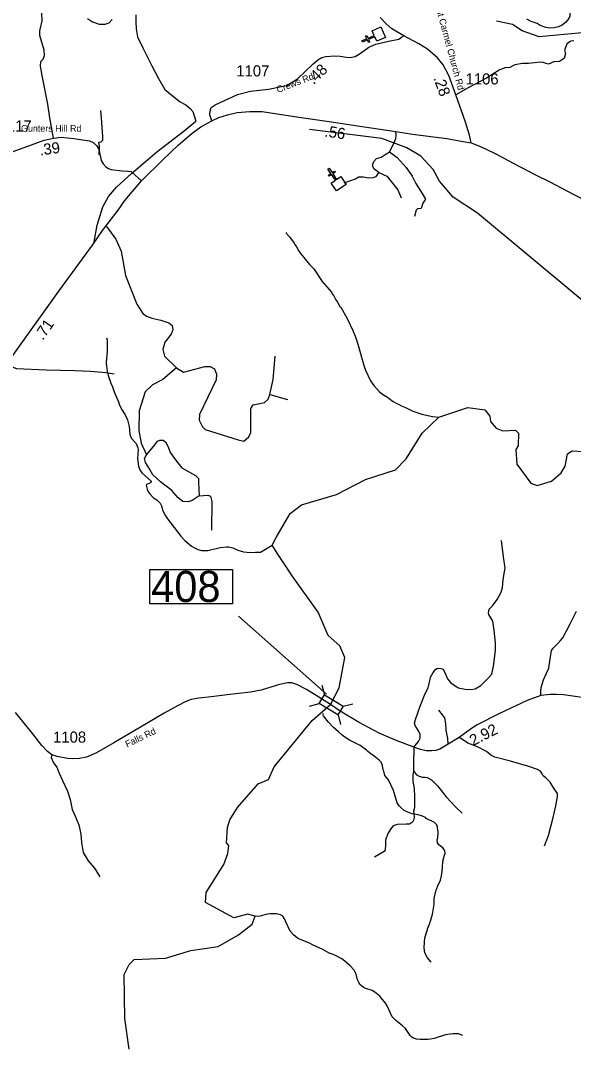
# Model space of a CAD drawing. Extents: x 1248089 to 1457196, y 820910 to 988753.
# Drawn here: x 1338152 to 1344378, y 848615 to 860169 of the extents above; entities that cross this region are included whole.
import ezdxf

# ---------------------------------------------------------------- set-up
doc = ezdxf.new("R2010")
doc.units = 0
for name, color, linetype in [('Exist Cultural Church CELL', 7, 'Continuous'), ('Exist Geographical Mountain Summit Label', 7, 'Continuous'), ('Exist Hydrographic Creek Single Shore', 7, 'Continuous'), ('Exist Hydrographic Misc Water Feature', 7, 'Continuous'), ('Exist Road Non-System Type 51', 7, 'Continuous'), ('Exist Road Primary NC Attributed', 7, 'Continuous'), ('Exist Road Secondary Structure Standard Bridge CELL', 7, 'Continuous'), ('Exist Road Secondary Structure Standard Bridge Number Label', 7, 'Continuous'), ('Exist Road Secondary Type 51 Attributed', 7, 'Continuous'), ('Exist Road Secondary Type 51 Label', 7, 'Continuous'), ('Prop CMT Slope Fill', 7, 'Continuous'), ('Prop GRAU CAT1 Cell', 7, 'Continuous'), ('Prop Lane Lines', 7, 'Continuous')]:
    doc.layers.add(name, color=color, linetype=linetype)

msp = doc.modelspace()

# ---------------------------------------------------------------- linework, layer by layer
at = {"layer": 'Exist Cultural Church CELL'}
for points in [[(1342164, 859935), (1342141, 859987), (1342071, 859957), (1342084, 859927), (1342069, 859921), (1342057, 859950), (1342001, 859926), (1341995, 859941), (1342050, 859965), (1342037, 859994), (1342052, 860001), (1342065, 859971), (1342135, 860002), (1342112, 860055), (1342209, 860097), (1342262, 859977)], [(1341650, 858339), (1341697, 858370), (1341655, 858434), (1341629, 858416), (1341620, 858429), (1341646, 858447), (1341613, 858497), (1341626, 858506), (1341660, 858456), (1341686, 858474), (1341695, 858460), (1341669, 858443), (1341711, 858379), (1341759, 858411), (1341818, 858323), (1341709, 858250)]]:
    msp.add_lwpolyline(points, close=True, dxfattribs=at)
at = {"layer": 'Exist Hydrographic Creek Single Shore'}
for points in [[(1341642, 852465), (1341739, 852654), (1341803, 852995), (1341747, 853127), (1341615, 853242), (1341503, 853505), (1341212, 853916), (1341125, 854046), (1341049, 854158), (1340984, 854262), (1341031, 854346), (1341187, 854619), (1341314, 854715), (1341708, 854832), (1342037, 854999), (1342373, 855110), (1342493, 855233), (1342674, 855521), (1342861, 855704), (1343189, 855810), (1343380, 855786), (1343437, 855713), (1343444, 855654), (1343509, 855577), (1343584, 855549), (1343726, 855556), (1343758, 855522), (1343755, 855378), (1343729, 855339), (1343742, 855172), (1343896, 854958), (1343970, 854934), (1344130, 854980), (1344240, 855076), (1344284, 855151), (1344312, 855291), (1344362, 855323), (1344487, 855314)], [(1340510, 851166), (1340597, 851305), (1340828, 851573), (1340946, 851623), (1341007, 851763), (1341436, 852287), (1341642, 852465)], [(1339377, 848583), (1339327, 848931), (1339321, 849424), (1339374, 849537), (1339433, 849595), (1339784, 849611), (1340069, 849697), (1340379, 849740), (1340607, 849871), (1340759, 849994), (1340793, 850081), (1340706, 850107), (1340555, 850063), (1340236, 850235), (1340243, 850351), (1340443, 850664), (1340485, 850789), (1340496, 850880), (1340471, 850907), (1340483, 851081), (1340510, 851166)]]:
    msp.add_lwpolyline(points, dxfattribs=at)
at = {"layer": 'Exist Hydrographic Misc Water Feature'}
for points in [[(1344475, 860032), (1343990, 859986), (1343800, 860055), (1343693, 860126), (1343510, 860163)], [(1345844, 854850), (1345727, 855194), (1345671, 855313), (1345336, 855629), (1345143, 855908), (1345055, 856110), (1344998, 856561), (1344926, 856681), (1344459, 857032), (1343296, 858000), (1343024, 858180), (1342870, 858360), (1342798, 858493), (1342659, 858640), (1342503, 858735), (1342222, 858839), (1341407, 858941)], [(1341142, 857781), (1341143, 857773), (1341180, 857732), (1341233, 857663), (1341240, 857646), (1341260, 857622), (1341287, 857573), (1341310, 857541), (1341407, 857423), (1341454, 857373), (1341547, 857231), (1341629, 857141), (1341652, 857109), (1341660, 857093), (1341679, 857068), (1341704, 857022), (1341722, 856999), (1341749, 856950), (1341757, 856942), (1341830, 856813), (1341893, 856679), (1341927, 856594), (1341949, 856526), (1342020, 856274), (1342037, 856232), (1342094, 856110), (1342129, 856058), (1342195, 855988), (1342238, 855955), (1342284, 855928), (1342349, 855880), (1342388, 855855), (1342422, 855841), (1342432, 855832), (1342485, 855811), (1342570, 855771), (1342670, 855735), (1342789, 855708), (1342861, 855704)], [(1339120, 856597), (1339126, 856573), (1339129, 856533), (1339127, 856445), (1339124, 856397), (1339119, 856375), (1339118, 856309), (1339128, 856221), (1339139, 856173), (1339169, 856084), (1339188, 856044), (1339206, 855987), (1339256, 855874), (1339263, 855850), (1339290, 855793), (1339329, 855728), (1339355, 855672), (1339376, 855599), (1339384, 855511), (1339391, 855487), (1339403, 855463), (1339453, 855405), (1339474, 855357), (1339476, 855341), (1339471, 855237), (1339479, 855149), (1339497, 855108), (1339518, 855076), (1339623, 854981), (1339622, 854972), (1339617, 854965), (1339609, 854958), (1339595, 854952), (1339579, 854948), (1339571, 854943), (1339567, 854935), (1339578, 854890), (1339593, 854858), (1339605, 854842), (1339651, 854795), (1339687, 854772), (1339724, 854733), (1339739, 854703), (1339756, 854646), (1339783, 854590), (1339806, 854557), (1339958, 854361), (1340003, 854312), (1340079, 854251), (1340119, 854226), (1340150, 854211), (1340190, 854200), (1340230, 854199), (1340262, 854202), (1340399, 854233), (1340471, 854243), (1340479, 854241), (1340495, 854243), (1340543, 854230), (1340598, 854204), (1340662, 854185), (1340742, 854177), (1340796, 854182), (1340854, 854182), (1340984, 854262)], [(1342776, 849563), (1342735, 849612), (1342704, 849669), (1342697, 849725), (1342699, 849791), (1342704, 849837), (1342734, 849932), (1342734, 849940), (1342760, 850003), (1342760, 850011), (1342768, 850027), (1342790, 850107), (1342809, 850218), (1342810, 850282), (1342819, 850330), (1342832, 850378), (1342841, 850393), (1342849, 850425), (1342879, 850488), (1342892, 850536), (1342901, 850584), (1342902, 850642), (1342907, 850696), (1342912, 850704), (1342912, 850720), (1342932, 850791), (1342930, 850815), (1342921, 850833), (1342907, 850852), (1342862, 850885), (1342848, 850909), (1342845, 850941), (1342849, 850965), (1342853, 851029), (1342843, 851105), (1342837, 851115), (1342813, 851138), (1342718, 851184), (1342711, 851192), (1342679, 851209), (1342631, 851224), (1342560, 851236), (1342520, 851249), (1342472, 851274), (1342437, 851303), (1342414, 851327), (1342394, 851360), (1342353, 851497), (1342296, 851618), (1342253, 851667), (1342242, 851715), (1342235, 851732), (1342226, 851780), (1342213, 851816), (1342189, 851841), (1342134, 851886), (1342095, 851911), (1342063, 851936), (1342048, 851952), (1341977, 852006), (1341858, 852063), (1341803, 852098), (1341756, 852135), (1341732, 852159), (1341673, 852211), (1341619, 852266), (1341562, 852340), (1341558, 852348), (1341559, 852366)], [(1343131, 848739), (1343115, 848747), (1343083, 848756), (1343020, 848759), (1342937, 848747), (1342810, 848706), (1342770, 848697), (1342738, 848694), (1342650, 848694), (1342610, 848697), (1342576, 848708), (1342557, 848720), (1342541, 848737), (1342485, 848816), (1342453, 848849), (1342379, 848909), (1342338, 848950), (1342317, 848990), (1342282, 849071), (1342263, 849103), (1342197, 849181), (1342142, 849226), (1342110, 849245), (1342039, 849269), (1342015, 849281), (1341988, 849302), (1341972, 849318), (1341960, 849334), (1341945, 849367), (1341930, 849431), (1341909, 849474), (1341865, 849525), (1341802, 849574), (1341770, 849603), (1341691, 849645), (1341644, 849662), (1341636, 849662), (1341549, 849712), (1341454, 849754), (1341398, 849784), (1341295, 849822), (1341272, 849835), (1341226, 849872), (1341189, 849913), (1341140, 850018), (1341126, 850052), (1341105, 850081), (1341081, 850099), (1341034, 850110), (1340960, 850110), (1340913, 850103), (1340865, 850086), (1340833, 850079), (1340793, 850081)]]:
    msp.add_lwpolyline(points, dxfattribs=at)
at = {"layer": 'Exist Road Non-System Type 51'}
msp.add_line((1340958, 855957), (1341157, 855902), dxfattribs=at)
for points in [[(1344045, 861034), (1344103, 860945), (1344175, 860858), (1344223, 860819), (1344273, 860798), (1344310, 860792), (1344349, 860775), (1344357, 860769), (1344368, 860748), (1344364, 860676), (1344353, 860564), (1344336, 860313), (1344338, 860220), (1344324, 860191), (1344291, 860150), (1344252, 860118), (1344210, 860100), (1344161, 860087), (1344113, 860085), (1344066, 860092), (1344001, 860112), (1343968, 860137), (1343900, 860160), (1343851, 860183)], [(1338483, 859075), (1338458, 859229), (1338397, 859550), (1338378, 859654), (1338381, 859707), (1338409, 859734), (1338424, 859777), (1338418, 859836), (1338369, 860002), (1338370, 860053), (1338397, 860167), (1338391, 860256), (1338345, 860382), (1338342, 860456)], [(1339450, 860235), (1339450, 860155), (1339453, 860075), (1339471, 859985), (1339530, 859862), (1339631, 859659), (1339704, 859516), (1339778, 859392), (1339861, 859325), (1339950, 859254), (1340015, 859220), (1340064, 859177), (1340092, 859143), (1340127, 859034)], [(1338905, 860192), (1338963, 860155), (1339037, 860130), (1339105, 860130), (1339151, 860145), (1339185, 860179)], [(1344380, 859941), (1344347, 859937), (1344332, 859931), (1344303, 859904), (1344295, 859883), (1344278, 859837), (1344289, 859798), (1344272, 859740), (1344243, 859722), (1344220, 859707), (1344158, 859703), (1344098, 859676), (1344072, 859685), (1344037, 859697), (1344004, 859699), (1343940, 859691), (1343871, 859687), (1343805, 859687), (1343716, 859670), (1343660, 859639), (1343605, 859637), (1343541, 859610), (1343398, 859521), (1343192, 859410), (1343055, 859332)], [(1338522, 858844), (1338483, 859075)], [(1339037, 858656), (1339040, 858749), (1339034, 858799), (1339061, 858802), (1339080, 858823), (1339080, 858860), (1339064, 859073), (1339058, 859156)], [(1339402, 858447), (1339531, 858554), (1339687, 858691), (1339994, 858928), (1340127, 859034)], [(1342306, 858692), (1342356, 858783), (1342379, 858839), (1342382, 858879), (1342379, 858918)], [(1342185, 858458), (1342129, 858499), (1342115, 858539), (1342132, 858582), (1342162, 858615), (1342212, 858632), (1342259, 858659), (1342306, 858692)], [(1342306, 858692), (1342392, 858626), (1342496, 858515), (1342563, 858418), (1342603, 858335), (1342676, 858221), (1342710, 858158), (1342683, 858111), (1342663, 858051), (1342623, 858047), (1342606, 858034), (1342589, 857964)], [(1338980, 857676), (1339014, 857863), (1339080, 858070), (1339144, 858186), (1339234, 858293), (1339402, 858447)], [(1341795, 858342), (1341922, 858385), (1341958, 858408), (1342012, 858408), (1342068, 858398), (1342122, 858402), (1342155, 858412), (1342169, 858428), (1342185, 858458)], [(1342185, 858458), (1342276, 858418), (1342312, 858375), (1342399, 858261), (1342436, 858174)], [(1339120, 857849), (1339224, 857706), (1339284, 857572), (1339334, 857298), (1339461, 856976), (1339529, 856871), (1339569, 856839), (1339630, 856817), (1339733, 856795), (1339821, 856765), (1339860, 856733), (1339868, 856687), (1339848, 856638), (1339777, 856547), (1339755, 856464), (1339773, 856391), (1339910, 856258)], [(1337996, 856304), (1338077, 856260), (1338106, 856250), (1338441, 856237), (1338764, 856227), (1338935, 856222), (1339115, 856206), (1339207, 856189)], [(1340958, 855957), (1340997, 856125), (1341020, 856391)], [(1339910, 856258), (1339754, 856125), (1339637, 856066), (1339555, 855988), (1339488, 855775), (1339485, 855554), (1339510, 855409), (1339569, 855277)], [(1339910, 856258), (1339988, 856211), (1340059, 856227), (1340227, 856274), (1340289, 856274), (1340336, 856246), (1340360, 856188), (1340356, 856121), (1340168, 855734), (1340164, 855667), (1340200, 855593), (1340230, 855564), (1340602, 855448), (1340665, 855433), (1340723, 855480), (1340747, 855530), (1340747, 855640), (1340747, 855800), (1340770, 855840), (1340829, 855851), (1340899, 855867), (1340942, 855906), (1340958, 855957)], [(1339569, 855277), (1339613, 855326), (1339664, 855392), (1339694, 855431), (1339721, 855444), (1339757, 855444), (1339784, 855424), (1339816, 855370), (1339838, 855306), (1339907, 855208), (1339970, 855130), (1340088, 855064), (1340122, 855046), (1340157, 855010), (1340157, 854968), (1340162, 854816), (1340162, 854816)], [(1340162, 854816), (1340083, 854764), (1340039, 854747), (1339980, 854752), (1339929, 854794), (1339855, 854877), (1339730, 854973), (1339642, 855054), (1339596, 855130), (1339561, 855193), (1339547, 855238), (1339569, 855277)], [(1340162, 854816), (1340213, 854821), (1340260, 854823), (1340291, 854813), (1340306, 854752), (1340304, 854428)], [(1342582, 851986), (1342632, 852051), (1342650, 852087), (1342650, 852101), (1342652, 852130), (1342632, 852169), (1342595, 852230), (1342589, 852255), (1342600, 852296), (1342652, 852448), (1342709, 852591), (1342740, 852654), (1342763, 852751), (1342770, 852775), (1342799, 852827), (1342824, 852859), (1342838, 852870), (1342856, 852877), (1342883, 852872), (1342912, 852863), (1342942, 852800), (1342960, 852757), (1342998, 852709), (1343044, 852675), (1343082, 852655), (1343157, 852639), (1343223, 852637), (1343270, 852643), (1343334, 852682), (1343420, 852766), (1343460, 852809), (1343479, 852897), (1343499, 853076), (1343501, 853158), (1343485, 853303), (1343469, 853405), (1343424, 853480), (1343420, 853500), (1343429, 853539), (1343467, 853577), (1343519, 853650), (1343562, 853730), (1343578, 853784), (1343587, 853871), (1343596, 853941), (1343607, 854000), (1343589, 854129), (1343569, 854312)], [(1344009, 852568), (1344010, 852617), (1344015, 852658), (1344042, 852746), (1344076, 852821), (1344099, 852875), (1344115, 852979), (1344130, 853075), (1344151, 853102), (1344196, 853145), (1344230, 853188), (1344257, 853217), (1344341, 853376), (1344411, 853516)], [(1342967, 852020), (1342965, 852085), (1342945, 852176), (1342940, 852251), (1342931, 852317), (1342902, 852351), (1342863, 852403)], [(1344051, 850874), (1344098, 850990), (1344148, 851192), (1344180, 851325), (1344198, 851432), (1344198, 851464), (1344162, 851518), (1344117, 851593), (1344067, 851640), (1344037, 851663), (1344026, 851686), (1344008, 851715), (1343974, 851736), (1343877, 851767), (1343668, 851828), (1343494, 851874), (1343448, 851896), (1343399, 851937), (1343299, 851989), (1343188, 852032), (1343127, 852073), (1343091, 852093)], [(1338506, 851901), (1338499, 851870), (1338523, 851810), (1338563, 851760), (1338583, 851699), (1338626, 851609), (1338683, 851492), (1338710, 851395), (1338733, 851285), (1338757, 851235)], [(1342582, 851986), (1342580, 851931), (1342575, 851850), (1342578, 851761), (1342575, 851718)], [(1342575, 851718), (1342569, 851676), (1342569, 851604), (1342585, 851522), (1342587, 851432), (1342587, 851305), (1342578, 851266), (1342580, 851239), (1342585, 851203), (1342582, 851171), (1342566, 851142), (1342530, 851119), (1342494, 851119), (1342392, 851114), (1342349, 851099), (1342329, 851078), (1342288, 851015), (1342263, 850938), (1342263, 850895), (1342259, 850827), (1342245, 850811), (1342139, 850746)], [(1342575, 851718), (1342609, 851676), (1342641, 851658), (1342673, 851647), (1342705, 851649), (1342732, 851645), (1342779, 851618), (1342847, 851552), (1342945, 851425), (1343058, 851305), (1343126, 851241)], [(1338757, 851235), (1338810, 851112), (1338830, 851005), (1338837, 850912), (1338857, 850801), (1338914, 850704), (1338987, 850624), (1339047, 850524)]]:
    msp.add_lwpolyline(points, dxfattribs=at)
at = {"layer": 'Exist Road Primary NC Attributed'}
for points in [[(1340307, 859041), (1340385, 859078), (1340482, 859109), (1340591, 859133), (1340735, 859145), (1340874, 859146), (1341287, 859081), (1341626, 859031), (1342000, 858974), (1342379, 858918), (1342566, 858889), (1342952, 858840), (1343115, 858811), (1343226, 858792)], [(1339513, 858365), (1339755, 858601), (1339930, 858769), (1340084, 858901), (1340183, 858972), (1340307, 859041)], [(1343226, 858792), (1343312, 858758), (1343396, 858722), (1343510, 858666), (1343699, 858561), (1343952, 858433), (1344113, 858352), (1344380, 858210), (1344689, 858051), (1344842, 857974), (1345181, 857816), (1345518, 857661), (1345712, 857587), (1345878, 857527), (1345995, 857492), (1346095, 857478), (1346181, 857475), (1346258, 857475), (1346367, 857487), (1346493, 857510), (1347001, 857667)], [(1337610, 855145), (1337717, 855736), (1337734, 855822), (1337760, 855909), (1337781, 855952), (1337805, 856006), (1337866, 856120), (1338105, 856448), (1338582, 857121), (1338962, 857639), (1339074, 857804), (1339252, 858034), (1339326, 858142), (1339513, 858365)]]:
    msp.add_lwpolyline(points, dxfattribs=at)
at = {"layer": 'Exist Road Secondary Structure Standard Bridge CELL'}
for p, q in [((1341546, 852686), (1341573, 852576)), ((1341404, 852449), (1341513, 852477)), ((1341785, 852448), (1341895, 852475)), ((1341727, 852351), (1341754, 852241))]:
    msp.add_line(p, q, dxfattribs=at)
msp.add_lwpolyline([(1341573, 852576), (1341786, 852448), (1341726, 852349), (1341513, 852477)], close=True, dxfattribs=at)
at = {"layer": 'Exist Road Secondary Structure Standard Bridge Number Label'}
msp.add_line((1341597, 852583), (1340607, 853463), dxfattribs=at)
msp.add_lwpolyline([(1339610, 853985), (1340539, 853985), (1340539, 853601), (1339610, 853601)], close=True, dxfattribs=at)
at = {"layer": 'Exist Road Secondary Type 51 Attributed'}
for points in [[(1342468, 859998), (1342332, 860075), (1342270, 860131), (1342201, 860205)], [(1340307, 859041), (1340283, 859109), (1340287, 859150), (1340299, 859190), (1340344, 859218), (1340595, 859336), (1340740, 859372), (1340944, 859398), (1341090, 859425), (1341160, 859443), (1341269, 859511), (1341442, 859678), (1341501, 859728), (1341546, 859754), (1341590, 859766), (1341690, 859771), (1341751, 859767), (1341844, 859752), (1341882, 859756), (1341921, 859763), (1341978, 859797), (1342074, 859869), (1342152, 859903), (1342295, 859936), (1342411, 859960), (1342441, 859981), (1342468, 859998)], [(1343226, 858792), (1343206, 858880), (1343162, 859023), (1343055, 859332), (1342974, 859551), (1342910, 859671), (1342846, 859750), (1342733, 859848), (1342637, 859905), (1342468, 859998)], [(1337583, 858564), (1337678, 858564), (1337805, 858593), (1338029, 858678), (1338305, 858779), (1338417, 858821), (1338522, 858844), (1338609, 858856), (1338751, 858840), (1338929, 858816), (1338969, 858797), (1339009, 858762), (1339033, 858721), (1339062, 858592), (1339083, 858554), (1339111, 858521), (1339144, 858504), (1339173, 858492), (1339298, 858475), (1339360, 858471), (1339397, 858469), (1339407, 858463), (1339513, 858365)], [(1341642, 852465), (1341570, 852513), (1341373, 852634), (1341263, 852691), (1341207, 852710), (1341158, 852710), (1341069, 852691), (1340861, 852627), (1340743, 852605), (1340477, 852574), (1340298, 852554), (1340161, 852538), (1340075, 852522), (1340015, 852502), (1339921, 852453), (1339768, 852367), (1339486, 852200), (1339267, 852074), (1339203, 852035), (1339009, 851921), (1338895, 851875), (1338815, 851859), (1338732, 851855), (1338680, 851860), (1338564, 851882), (1338506, 851901), (1338455, 851938), (1338394, 852006), (1338277, 852153), (1338094, 852378)], [(1344631, 852523), (1344264, 852575), (1344186, 852579), (1344116, 852580), (1344009, 852568), (1343856, 852512), (1343536, 852361), (1343293, 852237), (1343230, 852195), (1343091, 852093), (1342967, 852020), (1342874, 851965), (1342829, 851948), (1342783, 851943), (1342718, 851943), (1342655, 851960), (1342582, 851986), (1342373, 852065), (1342190, 852142), (1341964, 852262), (1341752, 852393), (1341642, 852465)]]:
    msp.add_lwpolyline(points, dxfattribs=at)

# ---------------------------------------------------------------- texts
at = {"layer": 'Exist Geographical Mountain Summit Label'}
msp.add_text('M  O  U  N  T  A  I  N  S', height=440, rotation=21.9503, dxfattribs=at).set_placement((1342480, 846813))
at = {"layer": 'Exist Road Secondary Structure Standard Bridge Number Label'}
msp.add_text('408', height=350, dxfattribs=at).set_placement((1339623, 853621))
at = {"layer": 'Exist Road Secondary Type 51 Label'}
for s, rotation, p in [('Mount Carmel Church Rd', 285.1872, (1342782, 860476)), ('Crews Rd', 21.365, (1341052, 859352)), ('Falls Rd', 25.7616, (1339353, 851981))]:
    msp.add_text(s, height=75, rotation=rotation, dxfattribs=at).set_placement(p)
msp.add_text('Gunters Hill Rd', height=75, dxfattribs=at).set_placement((1338158, 858917))
at = {"layer": 'Prop CMT Slope Fill'}
for s, rotation, p in [('.56', 351.3588, (1341570, 858865)), ('.71', 55.2052, (1338404, 856561))]:
    msp.add_text(s, height=125, rotation=rotation, dxfattribs=at).set_placement(p)
at = {"layer": 'Prop GRAU CAT1 Cell'}
for s, rotation, p in [('.48', 44.0909, (1341452, 859442)), ('.28', 290.338, (1342799, 859521)), ('.39', 7.6006, (1338373, 858649)), ('2.92', 27.0686, (1343247, 851997))]:
    msp.add_text(s, height=125, rotation=rotation, dxfattribs=at).set_placement(p)
at = {"layer": 'Prop Lane Lines'}
for s, p in [('1107', (1340582, 859540)), ('1106', (1343163, 859449)), ('1117', (1337906, 858919)), ('1108', (1338519, 852037))]:
    msp.add_text(s, height=125, dxfattribs=at).set_placement(p)

doc.saveas('drawing.dxf')
